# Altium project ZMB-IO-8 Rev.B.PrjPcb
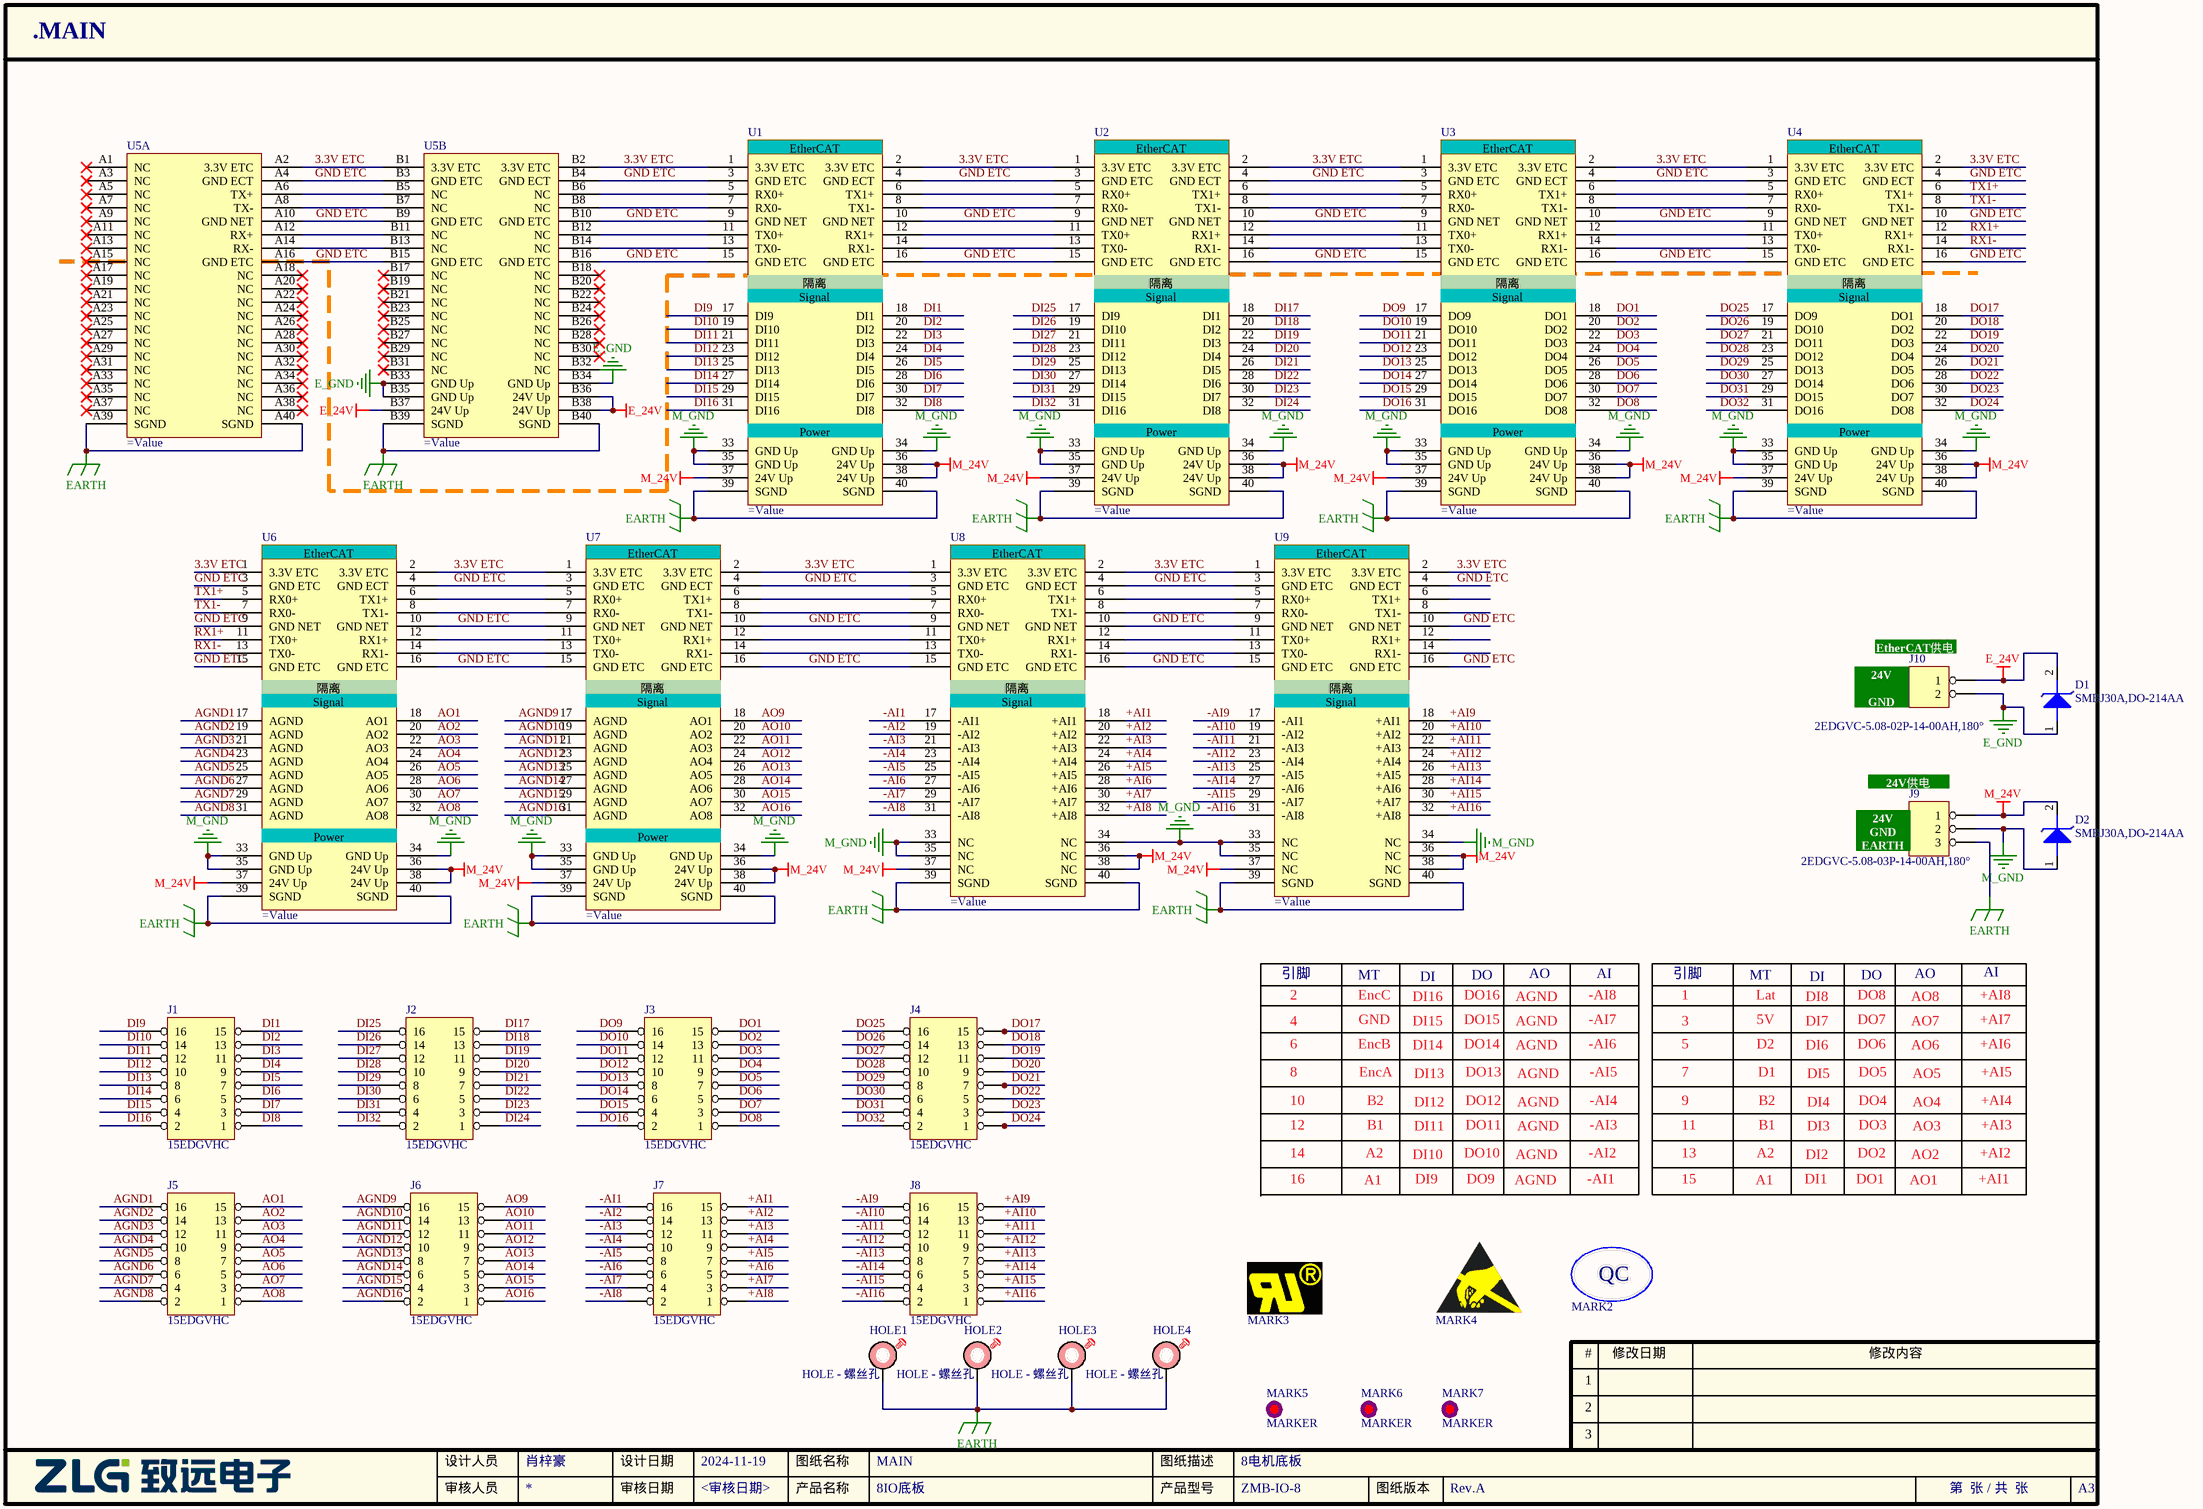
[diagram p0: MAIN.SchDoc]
1 sheet, 31 parts. Net scope: global (net labels, ports and power ports of the same name join across sheets).
Board file: ZMB-IO-8 Rev.B.PcbDoc

## Sheet MAIN.SchDoc
size A3; Author: 肖梓豪; PageSetup: Record=PageOptions¦CenterHorizontal=True¦CenterVertical=True¦PrintScale=1.00¦XCorrection=1.00¦YCorrection=1.00¦PrintKind=0¦BorderSize=5000000¦LeftOffset=0¦BottomOffset=0¦Orientation=2¦PaperLength=1000¦PaperWidth=1000¦Scale=100¦PaperSource=7¦PrintQuality=600¦MediaType=1¦DitherType=10¦PaperKind=A4¦PrintScaleMode=1; DesignDate: 2024-11-19; CheckDate: <审核日期>; SheetName: MAIN; SheetVersion: Rev.A; SheetDescription: 8电机底板; ProductName: 8IO底板; ProductModel: ZMB-IO-8

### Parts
D1  SMBJ30A,DO-214AA  [SOD-1812D]
D2  SMBJ30A,DO-214AA  [SOD-1812D]
HOLE1  HOLE - 螺丝孔  [HOLE-3.2 - Screw]  (no BOM)
HOLE2  HOLE - 螺丝孔  [HOLE-3.2 - Screw]  (no BOM)
HOLE3  HOLE - 螺丝孔  [HOLE-3.2 - Screw]  (no BOM)
HOLE4  HOLE - 螺丝孔  [HOLE-3.2 - Screw]  (no BOM)
J1  15EDGVHC  [DEGSON_15EDGVHC-THR-3.5-16P-1Y-1000Z(H)-PA]
J2  15EDGVHC  [DEGSON_15EDGVHC-THR-3.5-16P-1Y-1000Z(H)-PA]
J3  15EDGVHC  [DEGSON_15EDGVHC-THR-3.5-16P-1Y-1000Z(H)-PA]
J4  15EDGVHC  [DEGSON_15EDGVHC-THR-3.5-16P-1Y-1000Z(H)-PA]
J5  15EDGVHC  [DEGSON_15EDGVHC-THR-3.5-16P-1Y-1000Z(H)-PA]
J6  15EDGVHC  [DEGSON_15EDGVHC-THR-3.5-16P-1Y-1000Z(H)-PA]
J7  15EDGVHC  [DEGSON_15EDGVHC-THR-3.5-16P-1Y-1000Z(H)-PA]
J8  15EDGVHC  [DEGSON_15EDGVHC-THR-3.5-16P-1Y-1000Z(H)-PA]
J9  2EDGVC-5.08-03P-14-00AH,180°  [CON508P1664L820W140D35S-3DIP]
J10  2EDGVC-5.08-02P-14-00AH,180°  [CON508P1156L820W140D35S-2DIP]
MARK2  ZY QC  [ZY_QC]  (value not drawn)  (no BOM)
MARK3  UR  [ZY_UR-3X2]  (value not drawn)  (no BOM)
MARK4  ZY_ESD-MARK  [ZY_ESD-7]  (value not drawn)  (no BOM)
MARK5  MARKER  [MARKER-C-1.0M]  (no BOM)
MARK6  MARKER  [MARKER-C-1.0M]  (no BOM)
MARK7  MARKER  [MARKER-C-1.0M]  (no BOM)
U1  (no value)  [ZIOC-E1600DX]
U2  (no value)  [ZIOC-E1600DX]
U3  (no value)  [ZIOC-E0016DX]
U4  (no value)  [ZIOC-E0016DX]
U5  (no value)  [ZCPC-80801]  (parts A,B of 2)
U6  (no value)  [ZIOC-E0008AX]
U7  (no value)  [ZIOC-E0008AX]
U8  (no value)  [ZIOC-E0800AX]
U9  (no value)  [ZIOC-E0800AX]

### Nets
E_24V: D1.2 J10.1 U5.B36(24V_Up) U5.B37(24V_Up) U5.B38(24V_Up)
E_GND: D1.1 J10.2 U5.B33(GND_Up) U5.B34(GND_Up) U5.B35(GND_Up)
EARTH: HOLE1.1 HOLE2.1 HOLE3.1 HOLE4.1 J9.3 U1.39(SGND) U1.40(SGND) U2.39(SGND) U2.40(SGND) U3.39(SGND) U3.40(SGND) U4.39(SGND) U4.40(SGND) U5.A39(SGND) U5.A40(SGND) U5.B39(SGND) U5.B40(SGND) U6.39(SGND) U6.40(SGND) U7.39(SGND) U7.40(SGND) U8.39(SGND) U8.40(SGND) U9.39(SGND) U9.40(SGND)
M_24V: D2.2 J9.1 U1.36(24V_Up) U1.37(24V_Up) U1.38(24V_Up) U2.36(24V_Up) U2.37(24V_Up) U2.38(24V_Up) U3.36(24V_Up) U3.37(24V_Up) U3.38(24V_Up) U4.36(24V_Up) U4.37(24V_Up) U4.38(24V_Up) U6.36(24V_Up) U6.37(24V_Up) U6.38(24V_Up) U7.36(24V_Up) U7.37(24V_Up) U7.38(24V_Up) U8.36(NC) U8.37(NC) U8.38(NC) U9.36(NC) U9.37(NC) U9.38(NC)
M_GND: D2.1 J9.2 U1.33(GND_Up) U1.34(GND_Up) U1.35(GND_Up) U2.33(GND_Up) U2.34(GND_Up) U2.35(GND_Up) U3.33(GND_Up) U3.34(GND_Up) U3.35(GND_Up) U4.33(GND_Up) U4.34(GND_Up) U4.35(GND_Up) U6.33(GND_Up) U6.34(GND_Up) U6.35(GND_Up) U7.33(GND_Up) U7.34(GND_Up) U7.35(GND_Up) U8.33(NC) U8.34(NC) U8.35(NC) U9.33(NC) U9.34(NC) U9.35(NC)
3.3V ETC: U1.1(3.3V_ETC) U1.2(3.3V_ETC) U2.1(3.3V_ETC) U2.2(3.3V_ETC) U3.1(3.3V_ETC) U3.2(3.3V_ETC) U4.1(3.3V_ETC) U4.2(3.3V_ETC) U5.A2(3.3V_ETC) U5.B1(3.3V_ETC) U5.B2(3.3V_ETC) U6.1(3.3V_ETC) U6.2(3.3V_ETC) U7.1(3.3V_ETC) U7.2(3.3V_ETC) U8.1(3.3V_ETC) U8.2(3.3V_ETC) U9.1(3.3V_ETC) U9.2(3.3V_ETC)
+AI1: J7.15 U8.18(+AI1)
+AI2: J7.13 U8.20(+AI2)
+AI3: J7.11 U8.22(+AI3)
+AI4: J7.9 U8.24(+AI4)
+AI5: J7.7 U8.26(+AI5)
+AI6: J7.5 U8.28(+AI6)
+AI7: J7.3 U8.30(+AI7)
+AI8: J7.1 U8.32(+AI8)
+AI9: J8.15 U9.18(+AI1)
+AI10: J8.13 U9.20(+AI2)
+AI11: J8.11 U9.22(+AI3)
+AI12: J8.9 U9.24(+AI4)
+AI13: J8.7 U9.26(+AI5)
+AI14: J8.5 U9.28(+AI6)
+AI15: J8.3 U9.30(+AI7)
+AI16: J8.1 U9.32(+AI8)
-AI1: J7.16 U8.17(-AI1)
-AI2: J7.14 U8.19(-AI2)
-AI3: J7.12 U8.21(-AI3)
-AI4: J7.10 U8.23(-AI4)
-AI5: J7.8 U8.25(-AI5)
-AI6: J7.6 U8.27(-AI6)
-AI7: J7.4 U8.29(-AI7)
-AI8: J7.2 U8.31(-AI8)
-AI9: J8.16 U9.17(-AI1)
-AI10: J8.14 U9.19(-AI2)
-AI11: J8.12 U9.21(-AI3)
-AI12: J8.10 U9.23(-AI4)
-AI13: J8.8 U9.25(-AI5)
-AI14: J8.6 U9.27(-AI6)
-AI15: J8.4 U9.29(-AI7)
-AI16: J8.2 U9.31(-AI8)
AGND1: J5.16 U6.17(AGND)
AGND2: J5.14 U6.19(AGND)
AGND3: J5.12 U6.21(AGND)
AGND4: J5.10 U6.23(AGND)
AGND5: J5.8 U6.25(AGND)
AGND6: J5.6 U6.27(AGND)
AGND7: J5.4 U6.29(AGND)
AGND8: J5.2 U6.31(AGND)
AGND9: J6.16 U7.17(AGND)
AGND10: J6.14 U7.19(AGND)
AGND11: J6.12 U7.21(AGND)
AGND12: J6.10 U7.23(AGND)
AGND13: J6.8 U7.25(AGND)
AGND14: J6.6 U7.27(AGND)
AGND15: J6.4 U7.29(AGND)
AGND16: J6.2 U7.31(AGND)
AO1: J5.15 U6.18(AO1)
AO2: J5.13 U6.20(AO2)
AO3: J5.11 U6.22(AO3)
AO4: J5.9 U6.24(AO4)
AO5: J5.7 U6.26(AO5)
AO6: J5.5 U6.28(AO6)
AO7: J5.3 U6.30(AO7)
AO8: J5.1 U6.32(AO8)
AO9: J6.15 U7.18(AO1)
AO10: J6.13 U7.20(AO2)
AO11: J6.11 U7.22(AO3)
AO12: J6.9 U7.24(AO4)
AO13: J6.7 U7.26(AO5)
AO14: J6.5 U7.28(AO6)
AO15: J6.3 U7.30(AO7)
AO16: J6.1 U7.32(AO8)
DI1: J1.15 U1.18(DI1)
DI2: J1.13 U1.20(DI2)
DI3: J1.11 U1.22(DI3)
DI4: J1.9 U1.24(DI4)
DI5: J1.7 U1.26(DI5)
DI6: J1.5 U1.28(DI6)
DI7: J1.3 U1.30(DI7)
DI8: J1.1 U1.32(DI8)
DI9: J1.16 U1.17(DI9)
DI10: J1.14 U1.19(DI10)
DI11: J1.12 U1.21(DI11)
DI12: J1.10 U1.23(DI12)
DI13: J1.8 U1.25(DI13)
DI14: J1.6 U1.27(DI14)
DI15: J1.4 U1.29(DI15)
DI16: J1.2 U1.31(DI16)
DI17: J2.15 U2.18(DI1)
DI18: J2.13 U2.20(DI2)
DI19: J2.11 U2.22(DI3)
DI20: J2.9 U2.24(DI4)
DI21: J2.7 U2.26(DI5)
DI22: J2.5 U2.28(DI6)
DI23: J2.3 U2.30(DI7)
DI24: J2.1 U2.32(DI8)
DI25: J2.16 U2.17(DI9)
DI26: J2.14 U2.19(DI10)
DI27: J2.12 U2.21(DI11)
DI28: J2.10 U2.23(DI12)
DI29: J2.8 U2.25(DI13)
DI30: J2.6 U2.27(DI14)
DI31: J2.4 U2.29(DI15)
DI32: J2.2 U2.31(DI16)
DO1: J3.15 U3.18(DO1)
DO2: J3.13 U3.20(DO2)
DO3: J3.11 U3.22(DO3)
DO4: J3.9 U3.24(DO4)
DO5: J3.7 U3.26(DO5)
DO6: J3.5 U3.28(DO6)
DO7: J3.3 U3.30(DO7)
DO8: J3.1 U3.32(DO8)
DO9: J3.16 U3.17(DO9)
DO10: J3.14 U3.19(DO10)
DO11: J3.12 U3.21(DO11)
DO12: J3.10 U3.23(DO12)
DO13: J3.8 U3.25(DO13)
DO14: J3.6 U3.27(DO14)
DO15: J3.4 U3.29(DO15)
DO16: J3.2 U3.31(DO16)
DO17: J4.15 U4.18(DO1)
DO18: J4.13 U4.20(DO2)
DO19: J4.11 U4.22(DO3)
DO20: J4.9 U4.24(DO4)
DO21: J4.7 U4.26(DO5)
DO22: J4.5 U4.28(DO6)
DO23: J4.3 U4.30(DO7)
DO24: J4.1 U4.32(DO8)
DO25: J4.16 U4.17(DO9)
DO26: J4.14 U4.19(DO10)
DO27: J4.12 U4.21(DO11)
DO28: J4.10 U4.23(DO12)
DO29: J4.8 U4.25(DO13)
DO30: J4.6 U4.27(DO14)
DO31: J4.4 U4.29(DO15)
DO32: J4.2 U4.31(DO16)
GND ETC: U1.3(GND_ETC) U1.4(GND_ECT) U1.9(GND_NET) U1.10(GND_NET) U1.15(GND_ETC) U1.16(GND_ETC) U2.3(GND_ETC) U2.4(GND_ECT) U2.9(GND_NET) U2.10(GND_NET) U2.15(GND_ETC) U2.16(GND_ETC) U3.3(GND_ETC) U3.4(GND_ECT) U3.9(GND_NET) U3.10(GND_NET) U3.15(GND_ETC) U3.16(GND_ETC) U4.3(GND_ETC) U4.4(GND_ECT) U4.9(GND_NET) U4.10(GND_NET) U4.15(GND_ETC) U4.16(GND_ETC) U5.A4(GND_ECT) U5.A10(GND_NET) U5.A16(GND_ETC) U5.B3(GND_ETC) U5.B4(GND_ECT) U5.B9(GND_ETC) U5.B10(GND_ETC) U5.B15(GND_ETC) U5.B16(GND_ETC) U6.3(GND_ETC) U6.4(GND_ECT) U6.9(GND_NET) U6.10(GND_NET) U6.15(GND_ETC) U6.16(GND_ETC) U7.3(GND_ETC) U7.4(GND_ECT) U7.9(GND_NET) U7.10(GND_NET) U7.15(GND_ETC) U7.16(GND_ETC) U8.3(GND_ETC) U8.4(GND_ECT) U8.9(GND_NET) U8.10(GND_NET) U8.15(GND_ETC) U8.16(GND_ETC) U9.3(GND_ETC) U9.4(GND_ECT) U9.9(GND_NET) U9.10(GND_NET) U9.15(GND_ETC) U9.16(GND_ETC)
RX1+: U4.12(RX1+) U6.11(TX0+)
RX1-: U4.14(RX1-) U6.13(TX0-)
TX1+: U4.6(TX1+) U6.5(RX0+)
TX1-: U4.8(TX1-) U6.7(RX0-)
NetU1_5: U1.5(RX0+) U5.B6(NC)
NetU1_6: U1.6(TX1+) U2.5(RX0+)
NetU1_7: U1.7(RX0-) U5.B8(NC)
NetU1_8: U1.8(TX1-) U2.7(RX0-)
NetU1_11: U1.11(TX0+) U5.B12(NC)
NetU1_12: U1.12(RX1+) U2.11(TX0+)
NetU1_13: U1.13(TX0-) U5.B14(NC)
NetU1_14: U1.14(RX1-) U2.13(TX0-)
NetU2_6: U2.6(TX1+) U3.5(RX0+)
NetU2_8: U2.8(TX1-) U3.7(RX0-)
NetU2_12: U2.12(RX1+) U3.11(TX0+)
NetU2_14: U2.14(RX1-) U3.13(TX0-)
NetU3_6: U3.6(TX1+) U4.5(RX0+)
NetU3_8: U3.8(TX1-) U4.7(RX0-)
NetU3_12: U3.12(RX1+) U4.11(TX0+)
NetU3_14: U3.14(RX1-) U4.13(TX0-)
NetU5_A6: U5.A6(TX+) U5.B5(NC)
NetU5_A8: U5.A8(TX-) U5.B7(NC)
NetU5_A12: U5.A12(RX+) U5.B11(NC)
NetU5_A14: U5.A14(RX-) U5.B13(NC)
NetU6_6: U6.6(TX1+) U7.5(RX0+)
NetU6_8: U6.8(TX1-) U7.7(RX0-)
NetU6_12: U6.12(RX1+) U7.11(TX0+)
NetU6_14: U6.14(RX1-) U7.13(TX0-)
NetU7_6: U7.6(TX1+) U8.5(RX0+)
NetU7_8: U7.8(TX1-) U8.7(RX0-)
NetU7_12: U7.12(RX1+) U8.11(TX0+)
NetU7_14: U7.14(RX1-) U8.13(TX0-)
NetU8_6: U8.6(TX1+) U9.5(RX0+)
NetU8_8: U8.8(TX1-) U9.7(RX0-)
NetU8_12: U8.12(RX1+) U9.11(TX0+)
NetU8_14: U8.14(RX1-) U9.13(TX0-)

Not connected (* = marked no-connect by the designer): MARK5 0; MARK6 0; MARK7 0; U5 A1(NC)* A3(NC)* A5(NC)* A7(NC)* A9(NC)* A11(NC)* A13(NC)* A15(NC)* A17(NC)* A18(NC)* A19(NC)* A20(NC)* A21(NC)* A22(NC)* A23(NC)* A24(NC)* A25(NC)* A26(NC)* A27(NC)* A28(NC)* A29(NC)* A30(NC)* A31(NC)* A32(NC)* A33(NC)* A34(NC)* A35(NC)* A36(NC)* A37(NC)* A38(NC)* B17(NC)* B18(NC)* B19(NC)* B20(NC)* B21(NC)* B22(NC)* B23(NC)* B24(NC)* B25(NC)* B26(NC)* B27(NC)* B28(NC)* B29(NC)* B30(NC)* B31(NC)* B32(NC); U9 6(TX1+) 8(TX1-) 12(RX1+) 14(RX1-)

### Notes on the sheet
- (near J10) EtherCAT供电
- (near J10) 24V
  GND
- (near J9) 24V供电
- (near J9) 24V
  GND
  EARTH
- 引脚
- MT
- DI
- DO
- AO
- AI
- 6
- 4
- 2
- EncB
- EncC
- GND
- DI14
- DI15
- DI16
- DO14
- DO15
- DO16
- AGND
- -AI6
- -AI7
- -AI8
- 5
- 3
- 1
- Lat
- D2
- 5V
- DI6
- DI7
- DI8
- DO6
- DO7
- DO8
- AO6
- AO7
- AO8
- +AI6
- +AI7
- +AI8
- 10
- 8
- EncA
- B2
- DI12
- DI13
- DO12
- DO13
- -AI4
- -AI5
- 9
- 7
- D1
- DI4
- DI5
- DO4
- DO5
- AO4
- AO5
- +AI4
- +AI5
- 14
- 12
- 16
- A1
- A2
- B1
- DI10
- DI11
- DI9
- DO10
- DO11
- DO9
- -AI1
- -AI2
- -AI3
- 13
- 11
- 15
- DI1
- DI2
- DI3
- DO1
- DO2
- DO3
- AO1
- AO2
- AO3
- +AI1
- +AI2
- +AI3

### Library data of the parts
D1 D2 = 09.04.00227: SMBJ30A,DO-214AA,BRIGHTKING,; 旧物料代码: 1.04.03.0005; 名称: TVS瞬态抑制二极管; 封装: 1812; 贴片和直插: SMT; 环保状态: RoHS2.0; 器件优选方案: 可用; 生产单位: PCS
J1-J8 = HEADER 9X2_1
J9 = 19.04.00317: 2EDGVC-5.08-03P-14-00AH,180°,THT,DEGSON; 名称: 端子; PCB备注: 200701CZY201021lmd(PCB); 器件优选方案: 通用物料; 生产单位: PCS
J10 = 19.04.00316: 2EDGVC-5.08-02P-14-00AH,180°,THT,DEGSON; 名称: 端子; PCB备注: 200701CZY201021lmd(PCB); 器件优选方案: 通用物料; 生产单位: PCS
U1 U2 = ZIOC-E1600DX: 数字输入模组
U3 U4 = ZIOC-E0016DX: 数字输出模组
U5 = ZCPC-80801: 耦合器
U6 U7 = ZIOC-E0008AX: 模拟输出模组
U8 U9 = ZIOC-E0800AX: 模拟输入模组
